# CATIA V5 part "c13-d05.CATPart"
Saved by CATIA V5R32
Part number: Part1
Bounding box of the stored display mesh (mm): x -62.5 to 62.5, y -75 to 75, z 0 to 20
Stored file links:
  D:\PROJECTS\Project 2022\CATIA V5 6R 2022\Resources\Part Files\c13_catia_v5_6r2022_prt\c13_catia_v5-6r2022_figr_13-20\c13-d05.CATPart
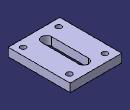
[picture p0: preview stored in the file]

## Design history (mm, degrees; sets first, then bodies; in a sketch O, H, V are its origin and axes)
Body1 (main body)
  Sketch1 on xy-plane, origin (0, 0, 0), H (1, 0, 0), V (0, 1, 0)
    line L1 (62.5, 75) -> (62.5, -75)
    line L2 (62.5, -75) -> (-62.5, -75)
    line L3 (-62.5, -75) -> (-62.5, 75)
    line L4 (-62.5, 75) -> (62.5, 75)
    length L1 = 150
    length L2 = 125
    vertical: L1 V, L3 V
    horizontal: L2 H, L4 H
    equidistance: L1 L3 O, L2 L4 O
  Pad1: profile Sketch1, direction (0, 0, 1), length 20
  Sketch2 on face of Pad1, origin (0, 0, 20), H (1, 0, 0), V (0, 1, 0)
    construction line L1 (0, 45) -> (0, -45)
    point P1 (0, 45)
    line L2 (12, 45) -> (12, -45)
    line L3 (-12, -45) -> (-12, 45)
    arc A1 centre (0, -45) radius 12 from (12, -45) to (-12, -45) cw
    arc A2 centre (0, 45) radius 12 from (-12, 45) to (12, 45) cw
    length L1 = 90
    radius A2 = 12
    coincidence: P1 V
    vertical: L1 V
    tangency: A1 L2, A2 L2, A1 L3, A2 L3
    parallelism: L1 L2
    midpoint: O L1
  Pocket1: profile Sketch2, direction (0, 0, -1), through (limit type 3)
  Sketch3 on face of Pad1, origin (38.7626, -18.4621, 20), H (1, 0, 0), V (0, 1, 0)
    point P1 (5.7374, -38.5379)
    reference projected line E1 (-101.2626, -56.5379) -> (23.7374, -56.5379) from edge [face of Pad1 | face of Pad1]
    reference projected line E2 (23.7374, -56.5379) -> (23.7374, 93.4621) from edge [face of Pad1 | face of Pad1]
    distance P1 E1 = 18
    distance P1 E2 = 18
  Hole1: placed by Sketch3, at (44.5, -57, 20) direction (0, 0, -1), diameter 13, through (limit type 3)
  RectPattern1: of Hole1, direction 1 instances 2, spacing 86, along edge [face of Pad1 | face of Pad1] reversed, direction 2 instances 2, spacing 112, along edge [face of Pad1 | face of Pad1]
